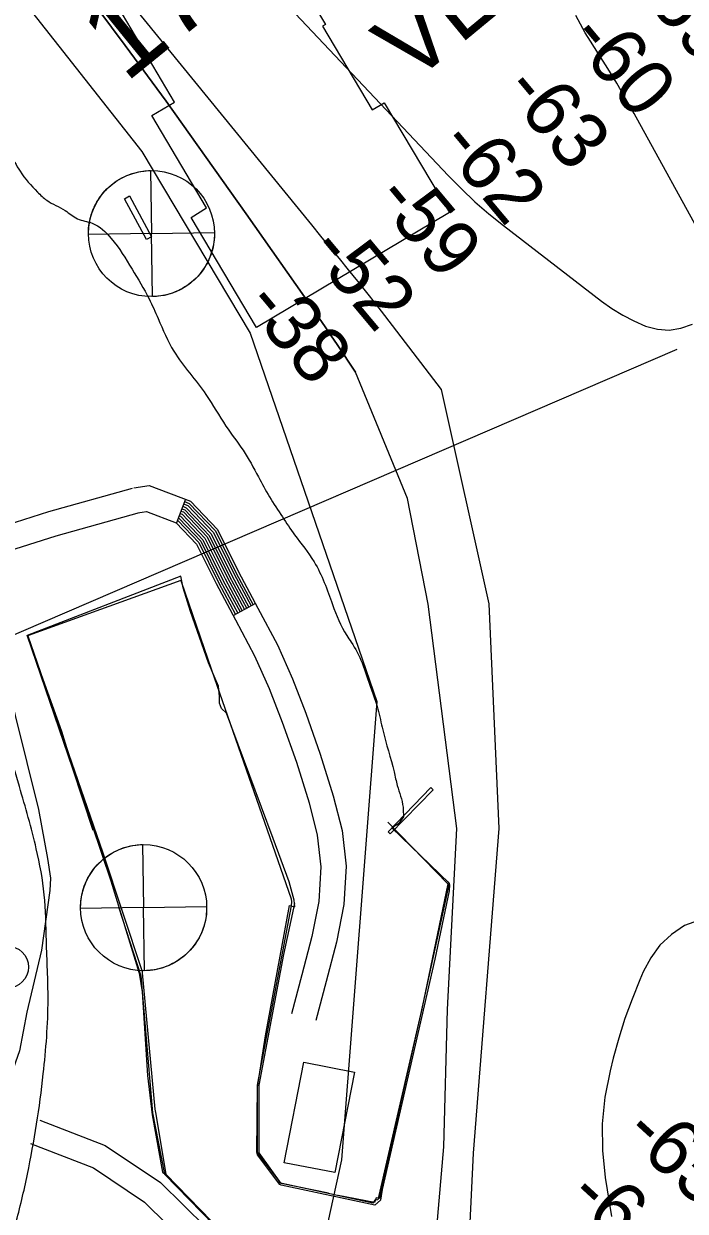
# Model space of a CAD drawing. Extents: x 3892998 to 3931244, y 278583 to 304547.
# Drawn here: x 3912353 to 3913140, y 286063 to 287475 of the extents above; entities that cross this region are included whole.
import ezdxf

# ---------------------------------------------------------------- set-up
doc = ezdxf.new("R2010")
doc.units = 0
for name, color, linetype in [('V-BLDG-OTLN', 7, 'Continuous'), ('V-CHAN-DOCK', 7, 'Continuous'), ('V-GRID-MAJR', 7, 'Continuous'), ('V-LEVE-TOET', 7, 'Continuous'), ('V-RIVR-EDGE', 7, 'Continuous'), ('V-RIVR-GAGE', 7, 'Continuous'), ('V-RIVR-GAGE-IDEN', 7, 'Continuous'), ('V-RIVR-RANG', 7, 'Continuous'), ('V-ROAD-CNTR', 7, 'Continuous'), ('V-RRAP-FSHR', 7, 'Continuous'), ('V-RRAP-RVMT', 7, 'Continuous'), ('V-SURV-IDEN', 7, 'Continuous'), ('V-SURV-LINE', 7, 'Continuous'), ('V-TOPO-DPTH', 7, 'Continuous'), ('V-TOPO-MAJR', 7, 'Continuous'), ('V-TOPO-MINR', 7, 'Continuous'), ('V-TOPO-SHOR', 7, 'Continuous')]:
    doc.layers.add(name, color=color, linetype=linetype)

msp = doc.modelspace()

# ---------------------------------------------------------------- linework, layer by layer
at = {"layer": 'V-BLDG-OTLN'}
msp.add_lwpolyline([(3912662.8, 286120.7), (3912686.2, 286240.2), (3912746.1, 286228.5), (3912722.7, 286109)], close=True, dxfattribs=at)
at = {"layer": 'V-CHAN-DOCK'}
for p, q in [((3912786.3, 286514.4), (3912837.2, 286566.8)), ((3912837.2, 286566.8), (3912839.7, 286564.4)), ((3912788.8, 286512), (3912839.7, 286564.4)), ((3912786.3, 286514.4), (3912788.8, 286512))]:
    msp.add_line(p, q, dxfattribs=at)
msp.add_lwpolyline([(3912498.7, 287218.7), (3912472.5, 287267.3), (3912478.6, 287270.5), (3912504.7, 287221.9), (3912498.7, 287218.7)], dxfattribs=at)
at = {"layer": 'V-GRID-MAJR'}
msp.add_spline([(3913205.7, 284291.2), (3913100.9, 290347.6), (3912996, 296407.6), (3912891.1, 302467.5), (3912891, 302471)], degree=3, dxfattribs=at)
at = {"layer": 'V-LEVE-TOET'}
msp.add_lwpolyline([(3912300, 286844.5), (3912306, 286800.7), (3912342.6, 286652.8), (3912370.2, 286540.8), (3912381, 286482.7), (3912384.6, 286459.3), (3912384, 286444.3), (3912374, 286373.5), (3912356.6, 286299.8), (3912347.7, 286253.7), (3912302.8, 286127.9), (3912266.3, 286032.6)], dxfattribs=at)
at = {"layer": 'V-RIVR-EDGE'}
for p, q in [((3912539.5, 286818.2), (3912356.7, 286747.8)), ((3912542.4, 286804.6), (3912539.5, 286818.2)), ((3912551, 286776.4), (3912542.4, 286804.6)), ((3912572.7, 286715.2), (3912551, 286776.4)), ((3912356.7, 286747.8), (3912397.7, 286634)), ((3912580.5, 286696.7), (3912572.7, 286715.2)), ((3912584.3, 286687.5), (3912580.5, 286696.7)), ((3912585.7, 286675.3), (3912584.3, 286687.5)), ((3912585.7, 286667.1), (3912585.7, 286675.3)), ((3912588.1, 286660.8), (3912585.7, 286667.1)), ((3912594, 286655.4), (3912588.1, 286660.8)), ((3912649.4, 286506.2), (3912594, 286655.4)), ((3912397.7, 286634), (3912410.7, 286591.3)), ((3912410.7, 286591.3), (3912456.5, 286456.1)), ((3912798.6, 286523.8), (3912790.8, 286518.9)), ((3912804.4, 286532), (3912798.6, 286523.8)), ((3912790.8, 286518.9), (3912859.1, 286453.2)), ((3912668.7, 286454.7), (3912649.4, 286506.2)), ((3912456.5, 286456.1), (3912475.8, 286392.5)), ((3912674.5, 286432.8), (3912668.7, 286454.7)), ((3912859.1, 286453.2), (3912824.7, 286296.9)), ((3912640.6, 286271.6), (3912669.1, 286426.5)), ((3912669.1, 286426.5), (3912675.5, 286425)), ((3912675.5, 286425), (3912674.5, 286432.8)), ((3912475.8, 286392.5), (3912490.2, 286346.3)), ((3912490.2, 286346.3), (3912493.6, 286324)), ((3912493.6, 286324), (3912500.1, 286224.4)), ((3912824.7, 286296.9), (3912774.1, 286076.6)), ((3912630.7, 286210.5), (3912640.6, 286271.6)), ((3912500.1, 286224.4), (3912505.4, 286177.8)), ((3912631, 286132.8), (3912630.7, 286210.5)), ((3912505.4, 286177.8), (3912517.8, 286109.3)), ((3912656.7, 286099.2), (3912631, 286132.8)), ((3912517.8, 286109.3), (3912523.1, 286105.8)), ((3912523.1, 286105.8), (3912533.8, 286094.6)), ((3912533.8, 286094.6), (3912564.8, 286063)), ((3912656.7, 286096.8), (3912656.7, 286099.2)), ((3912768.3, 286072.7), (3912656.7, 286096.8)), ((3912770.3, 286076.1), (3912768.3, 286072.7)), ((3912774.1, 286076.6), (3912770.3, 286076.1))]:
    msp.add_line(p, q, dxfattribs=at)
msp.add_spline([(3909865.8, 290928.2), (3909862.6, 290923.1), (3909860.7, 290922.6), (3909860.7, 290920.7), (3909870.3, 290905.1), (3909881.9, 290877.9), (3909893.5, 290856.5), (3909906.1, 290843.8), (3909921.6, 290817.6), (3909937.1, 290794.7), (3909948.2, 290777.2), (3909977.7, 290734.4), (3910003.4, 290694.5), (3910040.6, 290645.9), (3910078.4, 290595.3), (3910114.2, 290544.2), (3910151.5, 290493.6), (3910182, 290444.5), (3910200.8, 290413.3), (3910226.9, 290368.6), (3910256.9, 290323.8), (3910278.7, 290289.3), (3910307.7, 290250.4), (3910325.2, 290226.5), (3910363.9, 290167.2), (3910391.4, 290124.9), (3910427.7, 290068.9), (3910449.5, 290036.8), (3910504.2, 289956.6), (3910522.1, 289926.9), (3910550.1, 289879.7), (3910562.2, 289857.4), (3910573.3, 289842.3), (3910610.6, 289806.7), (3910620.8, 289794.1), (3910623.2, 289780), (3910634.8, 289764.4), (3910664.8, 289724), (3910692.4, 289689.5), (3910710.8, 289668.1), (3910721, 289660.3), (3910770.9, 289605.3), (3910782.5, 289588.7), (3910807.7, 289548.4), (3910835.7, 289503.6), (3910862.8, 289470), (3910892.3, 289425.8), (3910920.4, 289383.5), (3910948, 289342.6), (3910968.8, 289304.7), (3911000.2, 289260.9), (3911019.6, 289231.7), (3911055.9, 289191.3), (3911085.5, 289159.7), (3911118.9, 289116.8), (3911139.2, 289091.1), (3911161, 289062.3), (3911184.2, 289025.9), (3911223.4, 288981.6), (3911281.5, 288916.4), (3911313, 288876.9), (3911328.5, 288859.4), (3911346.4, 288837.5), (3911371.6, 288801), (3911404.5, 288751.9), (3911426.7, 288715.4), (3911446.6, 288687.7), (3911479, 288646.8), (3911529.4, 288582.1), (3911550.6, 288552.9), (3911609.2, 288468.3), (3911644.5, 288421.1), (3911677, 288378.8), (3911701.2, 288348.1), (3911741.4, 288303.8), (3911770.9, 288264.9), (3911788.8, 288235.7), (3911834.3, 288164.7), (3911857.5, 288130.2), (3911884.6, 288092.7), (3911915.6, 288045.5), (3911921.9, 288035.8), (3911928.6, 288029.9), (3911972.6, 287945.8), (3911992.9, 287906.4), (3912000.6, 287887), (3912014.7, 287866.5), (3912026.8, 287848.1), (3912066.4, 287785.3), (3912084.8, 287750.8), (3912094.5, 287732.8), (3912094.9, 287726), (3912096.8, 287711.4), (3912096.3, 287704.6), (3912095.4, 287700.3), (3912088.6, 287695.9), (3912085.6, 287696.9), (3912073, 287702.3), (3912062.4, 287706.2), (3912054.1, 287706.2), (3912051.2, 287704.3), (3912049.2, 287697.9), (3912054, 287685.8), (3912068.6, 287663.9), (3912113.1, 287586.6), (3912136.7, 287540.9), (3912153.7, 287513.6), (3912163.8, 287503.9), (3912187.6, 287479.6), (3912207.4, 287453.3), (3912216.1, 287446), (3912226.8, 287436.2), (3912240.8, 287416.8), (3912253.4, 287397.8), (3912271.3, 287366.2), (3912283.9, 287341.4), (3912284.8, 287339), (3912290.2, 287338), (3912303.8, 287344.3), (3912317.4, 287350.5), (3912319.8, 287350.5), (3912322.7, 287350.5), (3912327.6, 287345.7), (3912328.5, 287338.4), (3912335.8, 287321.4), (3912348.4, 287300), (3912369.2, 287275.1), (3912380.3, 287265.4), (3912402.1, 287253.2), (3912416.7, 287243.5), (3912434.2, 287238.1), (3912456.9, 287220), (3912481.6, 287183.6), (3912501.9, 287148.1), (3912512.6, 287124.7), (3912531.4, 287085.8), (3912550.3, 287059.6), (3912569.6, 287034.3), (3912593.3, 286996.8), (3912613.7, 286968.1), (3912632, 286936.5), (3912645.1, 286912.7), (3912660.6, 286888.8), (3912675.1, 286867.4), (3912698.3, 286835.3), (3912720.1, 286784.8), (3912737, 286747.8), (3912742.3, 286740), (3912755.3, 286715.2), (3912761.6, 286696.8), (3912774.1, 286660.3), (3912779.9, 286635.5), (3912793.4, 286585.5), (3912797.2, 286569.4), (3912804, 286543.7), (3912804.4, 286532)], degree=3, dxfattribs=at)
at = {"layer": 'V-RIVR-GAGE'}
for points in [[(3912503.5, 287300.8), (3912504.7, 287225.8), (3912429.7, 287224.6), (3912429.7, 287226.7), (3912429.8, 287229.3), (3912430, 287232.2), (3912430.3, 287235.2), (3912430.7, 287238), (3912431.2, 287241), (3912431.8, 287243.6), (3912432.5, 287246), (3912433.2, 287248.4), (3912434.1, 287251.1), (3912435, 287253.5), (3912436, 287255.8), (3912437.1, 287258.3), (3912438.5, 287261.1), (3912439.8, 287263.4), (3912441.2, 287265.7), (3912443.5, 287269.2), (3912445.2, 287271.4), (3912447.3, 287274.1), (3912449.4, 287276.5), (3912451.3, 287278.4), (3912454, 287281.1), (3912456.3, 287283.1), (3912458.7, 287285.1), (3912461.8, 287287.3), (3912464.1, 287288.9), (3912466.7, 287290.5), (3912469.6, 287292.1), (3912472.3, 287293.4), (3912474.8, 287294.6), (3912478.4, 287296.1), (3912481.7, 287297.2), (3912484.8, 287298.1), (3912488.1, 287298.9), (3912491.5, 287299.6), (3912495.5, 287300.2), (3912498.5, 287300.6), (3912501, 287300.7)], [(3912505.9, 287150.8), (3912504.7, 287225.8), (3912579.7, 287227.1), (3912579.7, 287224.4), (3912579.6, 287221.2), (3912579.4, 287218.6), (3912579.1, 287216), (3912578.6, 287212.9), (3912578, 287209.9), (3912577.2, 287206.6), (3912576.6, 287204.4), (3912575.7, 287201.5), (3912574.6, 287198.6), (3912573.5, 287196), (3912572.4, 287193.5), (3912571.2, 287191), (3912569.9, 287188.7), (3912568.3, 287186), (3912566.8, 287183.8), (3912564.7, 287180.9), (3912562.6, 287178.2), (3912560.1, 287175.2), (3912557.8, 287172.9), (3912555.4, 287170.5), (3912553.2, 287168.6), (3912551.6, 287167.3), (3912549, 287165.3), (3912547.1, 287163.9), (3912544.6, 287162.3), (3912542, 287160.7), (3912539.3, 287159.3), (3912537.2, 287158.2), (3912534.9, 287157.2), (3912532.3, 287156.1), (3912529.6, 287155.1), (3912526.4, 287154), (3912523.2, 287153.1), (3912520.8, 287152.6), (3912518.1, 287152), (3912515.7, 287151.6), (3912512.9, 287151.3), (3912510.7, 287151.1), (3912508.1, 287150.9)], [(3912494.2, 286499.1), (3912495.4, 286424.1), (3912420.4, 286422.9), (3912420.4, 286425), (3912420.5, 286427.6), (3912420.7, 286430.6), (3912421, 286433.6), (3912421.4, 286436.3), (3912422, 286439.3), (3912422.5, 286441.9), (3912423.2, 286444.3), (3912423.9, 286446.7), (3912424.8, 286449.5), (3912425.7, 286451.8), (3912426.7, 286454.1), (3912427.8, 286456.7), (3912429.2, 286459.4), (3912430.5, 286461.7), (3912431.9, 286464), (3912434.2, 286467.5), (3912435.9, 286469.8), (3912438.1, 286472.5), (3912440.2, 286474.9), (3912442, 286476.8), (3912444.7, 286479.4), (3912447, 286481.4), (3912449.4, 286483.4), (3912452.5, 286485.6), (3912454.9, 286487.2), (3912457.4, 286488.8), (3912460.4, 286490.4), (3912463, 286491.8), (3912465.6, 286492.9), (3912469.2, 286494.4), (3912472.4, 286495.5), (3912475.6, 286496.4), (3912478.8, 286497.2), (3912482.2, 286497.9), (3912486.2, 286498.5), (3912489.2, 286498.9), (3912491.8, 286499)], [(3912496.6, 286349.1), (3912495.4, 286424.1), (3912570.4, 286425.3), (3912570.4, 286422.6), (3912570.3, 286419.5), (3912570, 286416.9), (3912569.7, 286414.3), (3912569.3, 286411.1), (3912568.7, 286408.1), (3912567.9, 286404.8), (3912567.3, 286402.6), (3912566.3, 286399.8), (3912565.3, 286396.8), (3912564.2, 286394.3), (3912563.1, 286391.8), (3912561.8, 286389.3), (3912560.5, 286386.9), (3912558.9, 286384.2), (3912557.5, 286382), (3912555.4, 286379.1), (3912553.3, 286376.4), (3912550.7, 286373.5), (3912548.5, 286371.1), (3912546, 286368.8), (3912543.9, 286366.9), (3912542.3, 286365.5), (3912539.6, 286363.5), (3912537.7, 286362.2), (3912535.3, 286360.6), (3912532.6, 286359), (3912529.9, 286357.5), (3912527.8, 286356.5), (3912525.6, 286355.4), (3912523, 286354.4), (3912520.3, 286353.4), (3912517, 286352.3), (3912513.9, 286351.4), (3912511.5, 286350.8), (3912508.7, 286350.3), (3912506.3, 286349.9), (3912503.5, 286349.6), (3912501.4, 286349.3), (3912498.8, 286349.2)]]:
    msp.add_lwpolyline(points, close=True, dxfattribs=at)
for centre in [(3912504.7, 287225.8), (3912495.4, 286424.1)]:
    msp.add_circle(centre, 75, dxfattribs=at)
at = {"layer": 'V-RIVR-RANG'}
msp.add_line((3912266.9, 286716.7), (3913130.3, 287088.4), dxfattribs=at)
at = {"layer": 'V-ROAD-CNTR'}
for p, q in [((3912545.1, 286909.8), (3912534.4, 286881.8)), ((3912628.6, 286785.7), (3912602.2, 286771.5))]:
    msp.add_line(p, q, dxfattribs=at)
for points in [[(3912322.7, 286876.1), (3912382.7, 286895.1), (3912482.2, 286922.9)], [(3912483.7, 286923.2), (3912502, 286926.3), (3912551.3, 286907.5), (3912583.4, 286873.9), (3912608.3, 286823.3), (3912631.4, 286780.4), (3912654.5, 286736.5), (3912672.4, 286696.2), (3912688.4, 286655.2), (3912705.6, 286606.6), (3912721.1, 286557), (3912731.5, 286515.9), (3912736.5, 286473.6), (3912733.8, 286427.7), (3912724.9, 286383.1), (3912712.5, 286336.3), (3912700.2, 286290)], [(3912544.1, 286907), (3912549.6, 286904.9), (3912580.9, 286872.2), (3912605.6, 286822), (3912625.9, 286784.3)], [(3912269.7, 286827.9), (3912391.2, 286866.4), (3912490.3, 286894)], [(3912488.7, 286893.6), (3912499, 286895.4), (3912534.3, 286881.9), (3912558.5, 286856.5), (3912581.6, 286809.6), (3912604.9, 286766.3), (3912627.5, 286723.5), (3912644.7, 286684.6), (3912660.3, 286644.7), (3912677.1, 286597.2), (3912692.2, 286548.8), (3912702, 286510.4), (3912706.4, 286472.8), (3912704, 286431.5), (3912695.6, 286389.9), (3912683.5, 286344), (3912671.2, 286297.7)], [(3912538.7, 286893), (3912541.1, 286892.1), (3912568.4, 286863.5), (3912592.3, 286815.1), (3912612.7, 286777.2)], [(3912539.8, 286895.8), (3912542.8, 286894.7), (3912570.9, 286865.2), (3912595, 286816.5), (3912615.4, 286778.6)], [(3912540.9, 286898.6), (3912544.5, 286897.2), (3912573.4, 286866.9), (3912597.6, 286817.8), (3912618, 286780)], [(3912541.9, 286901.4), (3912546.2, 286899.8), (3912575.9, 286868.7), (3912600.3, 286819.2), (3912620.7, 286781.4)], [(3912543, 286904.2), (3912547.9, 286902.4), (3912578.4, 286870.4), (3912603, 286820.6), (3912623.3, 286782.9)], [(3912535.5, 286884.6), (3912536, 286884.4), (3912561, 286858.2), (3912584.3, 286811), (3912604.8, 286772.9)], [(3912536.6, 286887.4), (3912537.7, 286887), (3912563.5, 286860), (3912587, 286812.3), (3912607.4, 286774.3)], [(3912537.7, 286890.2), (3912539.4, 286889.6), (3912565.9, 286861.7), (3912589.6, 286813.7), (3912610.1, 286775.8)], [(3912371.8, 286171.4), (3912449.5, 286141.2), (3912515.4, 286097), (3912707, 285908.4)], [(3912360.9, 286143.5), (3912435.6, 286114.5), (3912496.4, 286073.7), (3912686, 285887)]]:
    msp.add_lwpolyline(points, dxfattribs=at)
msp.add_spline([(3912022.9, 285377.6), (3912061, 285425.8), (3912090.7, 285466.2), (3912119.1, 285515.7), (3912152.8, 285576.7), (3912183.9, 285646.7), (3912240.4, 285784.3), (3912292.7, 285909.1), (3912342.7, 286047.2), (3912357.2, 286107.1), (3912376, 286226.3), (3912381.7, 286314.9), (3912379.7, 286384.5), (3912377.2, 286439.5), (3912367.7, 286494), (3912347.6, 286568.2), (3912244.7, 286908.1), (3912215.2, 286998.6)], degree=3, dxfattribs=at)
at = {"layer": 'V-RRAP-FSHR'}
for points in [[(3912357.7, 287495.4), (3912493.3, 287323.3), (3912622.3, 287107.3), (3912773, 286669.1), (3912730.7, 286124.3), (3912615.3, 285598.2)], [(3912356.3, 286748.7), (3912410.6, 286589.5), (3912434.8, 286516.2)], [(3912786.1, 286525.9), (3912857.3, 286452.6), (3912826.6, 286303.6), (3912777.7, 286087.6), (3912776.1, 286078.2), (3912772.1, 286079), (3912770, 286073.4), (3912727, 286081.6)], [(3912465.4, 286425.2), (3912491.9, 286343.1), (3912506.1, 286180.1), (3912520.2, 286107), (3912638, 285986)], [(3912715.5, 286084.4), (3912659.1, 286096), (3912632.7, 286132.3), (3912632.7, 286212.9), (3912662.2, 286368.5), (3912675.3, 286429)]]:
    msp.add_lwpolyline(points, dxfattribs=at)
at = {"layer": 'V-RRAP-RVMT'}
for p, q in [((3912637.1, 287600.3), (3912711.8, 287474.4)), ((3912532.2, 287382.2), (3912465, 287495.3)), ((3912711.8, 287474.4), (3912708.2, 287472.3)), ((3912708.2, 287472.3), (3912767.2, 287372.9)), ((3912505.2, 287366.2), (3912532.2, 287382.2)), ((3912767.2, 287372.9), (3912781.5, 287381.4)), ((3912781.5, 287381.4), (3912859.2, 287251)), ((3912570.4, 287256.3), (3912505.2, 287366.2)), ((3912551.9, 287245.1), (3912570.4, 287256.3)), ((3912629.7, 287114.2), (3912551.9, 287245.1)), ((3912859.2, 287251), (3912629.7, 287114.2))]:
    msp.add_line(p, q, dxfattribs=at)
at = {"layer": 'V-SURV-LINE'}
msp.add_circle((3912333.4, 286353.4), 25, dxfattribs=at)
at = {"layer": 'V-TOPO-DPTH'}
for points in [[(3912747.3, 287060.8), (3912725.6, 287093.7), (3912718.6, 287104.3), (3912711.4, 287114.8), (3912704.2, 287125.3), (3912697, 287135.8), (3912617.3, 287249.4), (3912569.9, 287316.4), (3912522.1, 287383.1), (3912473.6, 287449.4), (3912424.8, 287515.4)], [(3913700.4, 285822.9), (3913577, 285862.7), (3913458.6, 285845.8), (3913325.6, 285813.8), (3913141.7, 285721.6), (3912993, 285733.9), (3912887.8, 285813.7), (3912833.9, 285924.1), (3912852.4, 286139.6), (3912857, 286302.9), (3912868.1, 286518.3), (3912833.8, 286784.9), (3912809.4, 286910.6), (3912747.3, 287060.8)]]:
    msp.add_lwpolyline(points, dxfattribs=at)
at = {"layer": 'V-TOPO-MAJR'}
for points in [[(3912325.3, 287689.9), (3912695.1, 287236.2), (3912706, 287222.8), (3912716.9, 287209.4), (3912727.9, 287196), (3912738.8, 287182.6), (3912749.7, 287169.2), (3912760.5, 287155.7), (3912771.2, 287142.1), (3912781.8, 287128.5), (3912849.6, 287040.3)], [(3912849.6, 287040.3), (3912906, 286785.3), (3912918, 286518.4), (3912887.6, 286132), (3912876.6, 285909.2), (3912922.4, 285835.7), (3912989.9, 285792.4), (3913079.1, 285786.5), (3913211.7, 285840.8), (3913337.1, 285887.5), (3913506.9, 285934.9), (3913618.7, 285907.2), (3913720.4, 285859.1)]]:
    msp.add_lwpolyline(points, dxfattribs=at)
at = {"layer": 'V-TOPO-MINR'}
for points in [[(3912568.3, 287601.7), (3912857.9, 287294.7), (3912873.5, 287278.9), (3912889.5, 287263.7), (3912906.3, 287249.3), (3912923.5, 287235.3), (3913040.2, 287145.5), (3913052.6, 287136.8), (3913065.4, 287128.8), (3913078.8, 287122), (3913092.7, 287115.8), (3913106.8, 287112.3), (3913120.8, 287111.1), (3913134.7, 287113.3), (3913148.5, 287117.9)], [(3912424.8, 287515.4), (3912473.6, 287449.4), (3912522.1, 287383.1), (3912569.9, 287316.4), (3912617.3, 287249.4), (3912697, 287135.8), (3912704.2, 287125.3), (3912711.4, 287114.8), (3912718.6, 287104.3), (3912725.6, 287093.7), (3912747.3, 287060.8)], [(3913166.6, 287209.1), (3913079, 287368.5), (3913068.8, 287386.6), (3913058.5, 287404.5), (3913047.7, 287422.2), (3913036.7, 287439.7), (3913027.1, 287454.7), (3913020.9, 287464.7), (3913015, 287474.9), (3913009.5, 287485.3)], [(3913700.4, 285822.9), (3913577, 285862.7), (3913458.6, 285845.8), (3913325.6, 285813.8), (3913141.7, 285721.6), (3912993, 285733.9), (3912887.8, 285813.7), (3912833.9, 285924.1), (3912852.4, 286139.6), (3912857, 286302.9), (3912868.1, 286518.3), (3912833.8, 286784.9), (3912809.4, 286910.6), (3912747.3, 287060.8)], [(3913155.5, 286408.9), (3913138.8, 286403), (3913123.3, 286392), (3913109.7, 286379.4), (3913098.8, 286364.4), (3913089.7, 286347.8), (3913085.6, 286338.3), (3913076.5, 286315.4), (3913068.1, 286292.3), (3913060.8, 286268.9), (3913054.2, 286245.2), (3913050.3, 286230.1), (3913044.3, 286198.6), (3913041, 286166.9), (3913041.5, 286135.1), (3913044.7, 286103.2), (3913052.2, 286056.8)]]:
    msp.add_lwpolyline(points, dxfattribs=at)
at = {"layer": 'V-TOPO-SHOR'}
msp.add_lwpolyline([(3912857.9, 286455.2), (3912859.5, 286451.3), (3912859.1, 286444), (3912841.8, 286363), (3912779.3, 286088.8), (3912777.2, 286076.2), (3912770.5, 286070.2), (3912659, 286094), (3912657.6, 286095), (3912631, 286130.2), (3912630.1, 286133.1), (3912630.8, 286212.4), (3912631.2, 286215.2), (3912671.2, 286426.4), (3912671.6, 286431.5), (3912671.2, 286434.3), (3912576.5, 286706.5), (3912540.3, 286811.5), (3912539.5, 286813.3), (3912358.6, 286747.9), (3912357.8, 286747.5), (3912446.8, 286489.4), (3912493.5, 286348.2), (3912493.7, 286346.7), (3912508.9, 286184.4), (3912510.1, 286178.3), (3912521.3, 286109), (3912521.9, 286107.1), (3912644.5, 285981)], dxfattribs=at)

# ---------------------------------------------------------------- texts
at = {"layer": 'V-RIVR-GAGE-IDEN'}
msp.add_text('VENICE GAGE', height=83, rotation=39.5219, dxfattribs=at).set_placement((3912814.5, 287402.8))
at = {"layer": 'V-RIVR-RANG'}
for s, rotation, p in [('-59', 309.98, (3913075.6, 287522.9)), ('-60', 309.98, (3912999.5, 287458.1)), ('-63', 309.98, (3912921.2, 287395.8)), ('-62', 309.98, (3912844.7, 287331.3)), ('-59', 309.98, (3912768.4, 287266.7)), ('-52', 309.98, (3912689.8, 287204.8)), ('-38', 309.98, (3912613.3, 287140.4)), ('-65', 317.5266, (3913063.9, 286151.9)), ('-64', 317.5266, (3912997.5, 286077.1))]:
    msp.add_text(s, height=67, rotation=rotation, dxfattribs=at).set_placement(p)
at = {"layer": 'V-SURV-IDEN'}
msp.add_text('1764+26.7', height=100, rotation=39.0902, dxfattribs=at).set_placement((3912473.5, 287403.9))

doc.saveas('drawing.dxf')
